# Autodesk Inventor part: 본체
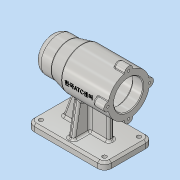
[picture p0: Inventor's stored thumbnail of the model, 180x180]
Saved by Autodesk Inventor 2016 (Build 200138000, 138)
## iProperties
Created: 2019-07
Part Number: 본체
Material: 알루미늄 6061
Document SubType Name: Modeling
Designer: Administrator
Density: 2.7 g/cm^3
Appearance: 알루미늄 - 평지
Mass: 644.123 g
Surface Area: 653.389 cm^2
Volume: 238.564 cm^3
Author: Administrator
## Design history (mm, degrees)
sketch "스케치1"
  geometry: L1 (-56, -35)-(56, -35); L2 (56, -35)-(56, 35); L3 (56, 35)-(-56, 35); L4 (-56, 35)-(-56, -35); L5 (-56, -35)-(56, 35); L6 (56, -35)-(-56, 35); 1 further point
  constraints: 12 end point, 2 midpoint, 2 parallel, 1 horizontal, 1 perpendicular
  dimensions: "d0" = 112 distance of L3.end L2.end; "d1" = 70 distance of L2.end L1.end
extrude "돌출1" new body sketch "스케치1" distance "d2" = 10; taper "d3" = 0 deg
sketch "스케치2"
  geometry: L1 (0, 0)-(0, 80); L2 (56, 80)-(-56, 80); L3 (-56, 80)-(-56, 110); L4 (-56, 110)-(11, 110); L5 (11, 110)-(31, 105); L6 (31, 105)-(56, 105); L7 (56, 105)-(56, 80)
  constraints: 14 end point, 2 perpendicular, 2 vertical, 1 horizontal, 1 midpoint, 1 parallel
  dimensions: "d4" = 80 distance of L1.end L1.start; "d5" = 112 distance of L2.start L2.end; "d7" = 60 diameter of L4 L2; "d8" = 25 distance of L5.end L6.end; "d9" = 45 distance from line of L4.end L7; "d10" = 50 diameter of L6 L2
revolve "회전1" sketch "스케치2" stored, may be unused: angle "d11" = 90 deg
sketch "스케치3"
  geometry: L1 (-56, 50)-(-56, 110) reference; L2 (-56, 80)-(50, 80); L3 (56, 55)-(56, 105) reference; L4 (-56, 80)-(-56, 101); L5 (-56, 101)-(-41, 101); L6 (-41, 101)-(-41, 104); L7 (-41, 104)-(13, 104); L8 (13, 104)-(13, 101); L9 (13, 101)-(25, 101); L10 (25, 101)-(25, 97.5); L11 (25, 97.5)-(43, 97.5); L12 (43, 97.5)-(43, 96); L13 (47, 96)-(47, 90.5); L14 (47, 90.5)-(50, 90.5); L15 (50, 90.5)-(50, 80); L16 (47, 96)-(43, 96); 1 further point
  constraints: 28 end point, 8 perpendicular, 2 horizontal, 1 midpoint, 1 point on line, 1 vertical
  dimensions: "d12" = 15 distance of L4.end L5.end; "d13" = 3 distance of L13.end L14.end; "d15" = 18 distance of L10.end L11.end; "d16" = 12 distance of L8.end L9.end; "d17" = 54 distance of L6.end L7.end; "d19" = 106 distance of L2.start L2.end; "d20" = 21 diameter of L14 L2; "d21" = 35 diameter of L11 L2; "d22" = 32 diameter of L16 L2; "d23" = 42 diameter of L9 L2; "d24" = 48 diameter of L7 L2; "d25" = 42 diameter of L5 L2
revolve "회전2" sketch "스케치3" stored, may be unused: angle "d26" = 90 deg
sketch "스케치4"
  geometry: L1 (56, 35)-(-56, 35) reference; L2 (0, 35)-(0, -35); L3 (-56, -35)-(56, -35) reference; L4 (56, -35)-(56, 35) reference; L5 (56, 0)-(-56, 0); L6 (-56, 35)-(-56, -35) reference; L7 (-4, -4)-(4, -4); L8 (4, -4)-(4, 4); L9 (4, 4)-(-4, 4); L10 (-4, 4)-(-4, -4); L11 (-4, -4)-(4, 4); L12 (4, -4)-(-4, 4); 1 further point
  constraints: 16 end point, 6 midpoint, 2 parallel, 1 horizontal, 1 perpendicular
  dimensions: "d27" = 8 distance of L9.end L8.end; "d28" = 8 distance of L8.end L7.end
extrude "돌출2" join sketch "스케치4" stored distance "d29" = 10; taper "d30" = 0 deg
sketch "스케치5"
  geometry: L1 (-56, 10)-(56, 10) reference; L2 (-31, 10)-(-31, 40); L3 (-56, 0)-(-56, 10) reference; 1 further point
  constraints: 2 end point, 1 point on line, 1 vertical
  dimensions: "d31" = 25 distance between parallel lines of L2 L3; "d32" = 30 distance of L2.start L2.end
feature "리브1" sketch "스케치5" dims "d33" = 1, "d34" = 8, "d35" = 0, "d36" = 0, "d37" = 1, "d38" = 1
sketch "스케치6"
  geometry: L1 (-56, 10)-(56, 10) reference; L2 (36, 10)-(24.029, 42.889); L3 (56, 0)-(56, 10) reference; 1 further point
  constraints: 2 end point, 1 point on line
  dimensions: "d39" = 35 distance of L2.start L2.end; "d40" = 20 distance from line of L2.start L3; "d41" = 110 deg angle of L1 L2
feature "리브2" sketch "스케치6" dims "d42" = 1, "d43" = 8, "d44" = 0, "d45" = 0, "d46" = 1, "d47" = 1
sketch "스케치7"
  geometry: L1 (35, 10)-(-35, 10) reference; L2 (28, 10)-(22.791, 39.544); L3 (35, 0)-(35, 10) reference; 1 further point
  constraints: 2 end point, 1 point on line
  dimensions: "d48" = 30 distance of L2.start L2.end; "d49" = 7 distance from line of L2.start L3; "d50" = 100 deg angle of L2 L1
feature "리브3" sketch "스케치7" dims "d51" = 1, "d52" = 8, "d53" = 0, "d54" = 0, "d55" = 1, "d56" = 1
sketch "스케치8"
  geometry: C1 r 6 at (-30, 0); 2 further points
  constraints: 2 horizontal alignment, 1 centre point, 1 other
  dimensions: "d57" = 6 radius of C1
extrude "돌출3" join sketch "스케치8" distance "d58" = 16; taper "d59" = 0 deg
sketch "스케치9"
  geometry: A1 r 6 centre (0, 0) between (0.6, 5.97) and (0.6, -5.97) reference; A2 r 6 centre (30, 30) between (35.97, 29.4) and (24.03, 29.4) reference; A3 r 6 centre (60, 0) between (59.4, -5.97) and (59.4, 5.97) reference; A4 r 6 centre (30, -30) between (24.03, -29.4) and (35.97, -29.4) reference; 5 further points
  constraints: 4 coincident
hole "구멍1" sketch "스케치9" at (30, -30), (60, 0), (30, 30), (0, 0) diameter "d63" = 3.242; stored, may be unused: countersink angle "d67" = 90 deg, drill point angle "d69" = 118 deg; dims "d64" = 8, "d65" = 4, "d66" = 2, "d68" = 11
fillet "모깎기1" dims "d70" = 10
sketch "스케치10"
  geometry: C1 r 3 at (-46, 25); C2 r 3 at (-46, -25); C3 r 3 at (46, -25); C4 r 3 at (46, 25); A1 r 10 centre (-46, 25) between (-46, 35) and (-56, 25) reference; A2 r 10 centre (-46, -25) between (-56, -25) and (-46, -35) reference; A3 r 10 centre (46, -25) between (46, -35) and (56, -25) reference; A4 r 10 centre (46, 25) between (56, 25) and (46, 35) reference; 1 further point
  constraints: 4 centre point, 4 coincident
  dimensions: "d71" = 6 diameter of C1; "d72" = 6 diameter of C2; "d73" = 6 diameter of C3; "d74" = 6 diameter of C4
extrude "돌출4" cut sketch "스케치10" stored distance "d75" = 16; taper "d76" = 0 deg
fillet "모깎기2" dims "d77" = 10
fillet "모깎기3" dims "d78" = 3
fillet "모깎기4" dims "d79" = 3
fillet "모깎기5" dims "d80" = 1
fillet "모깎기6" dims "d84" = 3
fillet "모깎기7" dims "d85" = 3
fillet "모깎기8" dims "d86" = 3
chamfer "모따기1" distance "d87" = 3; stored, may be unused: second distance "d88" = 2, angle "d89" = 45 deg
chamfer "모따기2" distance "d90" = 1; stored, may be unused: second distance "d91" = 2, angle "d92" = 45 deg
fillet "모깎기9" dims "d93" = 3
fillet "모깎기10" dims "d94" = 3
fillet "모깎기11" dims "d95" = 0.3
node "작업 평면1"
sketch "스케치11"
  geometry: L1 (56, 58)-(56, 102) reference; L2 (56, 80)-(-56, 80); L3 (-56, 65)-(-56, 95) reference; 2 further points
  constraints: 2 end point, 2 midpoint, 1 point on line, 1 other
  dimensions: "d97" = 42 distance from line of point (14, 80) L1
feature "엠보싱1" sketch "스케치11" dims "d98" = 0.5, "d99" = 0
node "솔리드1"
mirror "대칭1"
pattern_circular "원형 패턴1" dims angle "d61" = 360 deg
pattern_circular "원형 패턴2" dims angle "d82" = 360 deg
